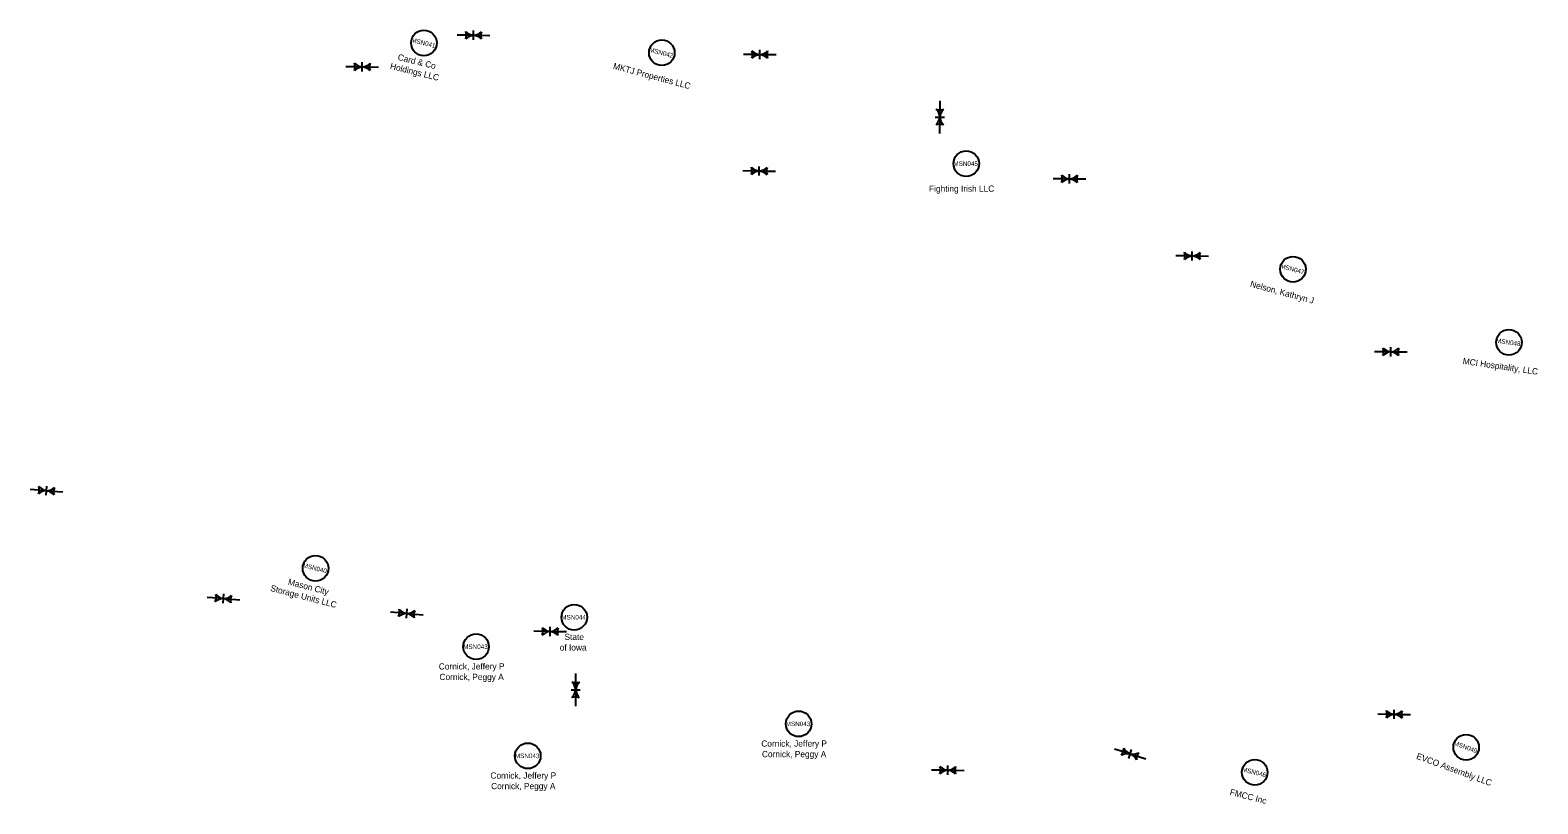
# Model space of a CAD drawing. Extents: x 4995262 to 4999253, y 3881150 to 3900196.
# Drawn here: x 4998411 to 4999235, y 3881150 to 3881573 of the extents above; entities that cross this region are included whole.
import ezdxf

# ---------------------------------------------------------------- set-up
doc = ezdxf.new("R2010")
doc.units = 0
doc.layers.add('NamedBoundary', color=7, linetype='Continuous')
doc.layers.add('SheetText', color=7, linetype='Continuous')

msp = doc.modelspace()

# ---------------------------------------------------------------- linework, layer by layer
at = {"layer": 'NamedBoundary'}
for centre in [(4998626.57, 3881565.83), (4998756.56, 3881560.46), (4998922.88, 3881499.86), (4999101.39, 3881442.16), (4999219.38, 3881402.24), (4998567.37, 3881278.73), (4998708.71, 3881251.99), (4998655.1, 3881235.88), (4998831.3, 3881193.71), (4998683.33, 3881176.23), (4999196.01, 3881180.91), (4999080.5, 3881167.23)]:
    msp.add_circle(centre, 7, dxfattribs=at)
at = {"layer": 'SheetText'}
for p, q in [((4998653.73, 3881570.02), (4998644.78, 3881570.06)), ((4998653.72, 3881567.48), (4998653.74, 3881572.55)), ((4998653.73, 3881570.02), (4998662.67, 3881569.97)), ((4998810.05, 3881556.94), (4998810.07, 3881562)), ((4998592.89, 3881552.71), (4998583.95, 3881552.75)), ((4998592.88, 3881550.18), (4998592.9, 3881555.24)), ((4998592.89, 3881552.71), (4998601.83, 3881552.67)), ((4998810.06, 3881559.47), (4998801.12, 3881559.51)), ((4998810.06, 3881559.47), (4998819, 3881559.43)), ((4998908.47, 3881525.32), (4998908.59, 3881534.26)), ((4998905.94, 3881525.35), (4998911, 3881525.29)), ((4998908.47, 3881525.32), (4998908.35, 3881516.38)), ((4998809.77, 3881495.83), (4998800.83, 3881495.88)), ((4998809.76, 3881493.3), (4998809.78, 3881498.37)), ((4998809.77, 3881495.83), (4998818.71, 3881495.79)), ((4998979.28, 3881488.99), (4998979.3, 3881494.05)), ((4998979.29, 3881491.52), (4998970.35, 3881491.56)), ((4998979.29, 3881491.52), (4998988.23, 3881491.48)), ((4999046.35, 3881449.41), (4999037.41, 3881449.45)), ((4999046.34, 3881446.88), (4999046.36, 3881451.94)), ((4999046.35, 3881449.41), (4999055.29, 3881449.37)), ((4999154.84, 3881397.02), (4999145.9, 3881397.04)), ((4999154.83, 3881394.48), (4999154.85, 3881399.55)), ((4999154.84, 3881397.02), (4999163.78, 3881396.99)), ((4998420.38, 3881321.14), (4998411.46, 3881321.8)), ((4998420.19, 3881318.62), (4998420.57, 3881323.66)), ((4998420.38, 3881321.14), (4998429.3, 3881320.48)), ((4998516.85, 3881259.63), (4998517.23, 3881264.68)), ((4998517.04, 3881262.16), (4998508.12, 3881262.83)), ((4998517.04, 3881262.16), (4998525.96, 3881261.48)), ((4998616.98, 3881251.46), (4998617.36, 3881256.5)), ((4998617.17, 3881253.98), (4998608.25, 3881254.66)), ((4998617.17, 3881253.98), (4998626.09, 3881253.3)), ((4998695.55, 3881244.19), (4998686.61, 3881244.28)), ((4998695.53, 3881241.66), (4998695.58, 3881246.72)), ((4998695.55, 3881244.19), (4998704.5, 3881244.11)), ((4998709.5, 3881212.33), (4998709.62, 3881221.27)), ((4998706.97, 3881212.36), (4998712.04, 3881212.29)), ((4998709.5, 3881212.33), (4998709.39, 3881203.38)), ((4999156.68, 3881198.91), (4999147.74, 3881198.98)), ((4999156.66, 3881196.38), (4999156.7, 3881201.44)), ((4999156.68, 3881198.91), (4999165.63, 3881198.84)), ((4999012.42, 3881177.27), (4999003.86, 3881179.86)), ((4999011.68, 3881174.85), (4999013.15, 3881179.69)), ((4999012.42, 3881177.27), (4999020.97, 3881174.67)), ((4998912.79, 3881168.37), (4998903.85, 3881168.45)), ((4998912.77, 3881165.84), (4998912.82, 3881170.9)), ((4998912.79, 3881168.37), (4998921.74, 3881168.29))]:
    msp.add_line(p, q, dxfattribs=at)
for centre, radius, start, end in [((4998644.13, 3881570.06), 5.68, 339.12989, 20.34353), ((4998654.47, 3881562.76), 7.29, 95.84257, 133.64981), ((4998654.54, 3881577.26), 7.29, 225.82361, 263.63086), ((4998652.99, 3881577.27), 7.29, 275.84257, 313.64981), ((4998652.92, 3881562.77), 7.29, 45.82361, 83.63086), ((4998663.32, 3881569.97), 5.68, 159.12989, 200.34353), ((4998800.46, 3881559.51), 5.68, 339.1317, 20.34534), ((4998810.87, 3881566.72), 7.29, 225.82542, 263.63267), ((4998809.32, 3881566.73), 7.29, 275.84437, 313.65162), ((4998819.66, 3881559.43), 5.68, 159.1317, 200.34534), ((4998583.29, 3881552.75), 5.68, 339.12989, 20.34353), ((4998593.63, 3881545.45), 7.29, 95.84257, 133.64981), ((4998593.7, 3881559.96), 7.29, 225.82361, 263.63086), ((4998592.15, 3881559.97), 7.29, 275.84257, 313.64981), ((4998592.08, 3881545.46), 7.29, 45.82361, 83.63086), ((4998602.49, 3881552.67), 5.68, 159.12989, 200.34353), ((4998810.8, 3881552.21), 7.29, 95.84437, 133.65162), ((4998809.25, 3881552.22), 7.29, 45.82542, 83.63267), ((4998901.21, 3881524.64), 7.29, 5.34157, 43.14881), ((4998908.6, 3881534.91), 5.68, 248.62889, 289.84253), ((4998915.71, 3881524.45), 7.29, 135.32261, 173.12986), ((4998901.23, 3881526.19), 7.29, 315.32261, 353.12986), ((4998908.34, 3881515.72), 5.68, 68.62889, 109.84253), ((4998915.73, 3881526), 7.29, 185.34157, 223.14881), ((4998800.17, 3881495.88), 5.68, 339.13243, 20.34607), ((4998810.51, 3881488.58), 7.29, 95.84511, 133.65235), ((4998810.58, 3881503.08), 7.29, 225.82615, 263.6334), ((4998809.03, 3881503.09), 7.29, 275.84511, 313.65235), ((4998808.96, 3881488.59), 7.29, 45.82615, 83.6334), ((4998819.37, 3881495.79), 5.68, 159.13243, 200.34607), ((4998969.69, 3881491.56), 5.68, 339.1317, 20.34534), ((4998980.03, 3881484.26), 7.29, 95.84437, 133.65162), ((4998980.1, 3881498.77), 7.29, 225.82542, 263.63267), ((4998978.55, 3881498.78), 7.29, 275.84437, 313.65162), ((4998978.48, 3881484.27), 7.29, 45.82542, 83.63267), ((4998988.89, 3881491.48), 5.68, 159.1317, 200.34534), ((4999036.75, 3881449.45), 5.68, 339.1317, 20.34534), ((4999047.09, 3881442.15), 7.29, 95.84437, 133.65162), ((4999047.16, 3881456.66), 7.29, 225.82542, 263.63267), ((4999045.61, 3881456.67), 7.29, 275.84437, 313.65162), ((4999045.54, 3881442.16), 7.29, 45.82542, 83.63267), ((4999055.95, 3881449.37), 5.68, 159.1317, 200.34534), ((4999145.24, 3881397.05), 5.68, 339.21749, 20.43113), ((4999155.59, 3881389.76), 7.29, 95.93016, 133.73741), ((4999155.64, 3881404.27), 7.29, 225.91121, 263.71846), ((4999154.09, 3881404.27), 7.29, 275.93016, 313.73741), ((4999154.04, 3881389.77), 7.29, 45.91121, 83.71846), ((4999164.44, 3881396.99), 5.68, 159.21749, 200.43113), ((4998410.81, 3881321.84), 5.68, 335.19079, 16.40442), ((4998420.62, 3881313.85), 7.29, 91.90346, 129.7107), ((4998421.69, 3881328.32), 7.29, 221.8845, 259.69175), ((4998420.14, 3881328.43), 7.29, 271.90346, 309.7107), ((4998419.07, 3881313.96), 7.29, 41.8845, 79.69175), ((4998429.95, 3881320.44), 5.68, 155.19079, 196.40442), ((4998507.47, 3881262.88), 5.68, 335.04604, 16.25967), ((4998518.36, 3881269.33), 7.29, 221.73975, 259.547), ((4998516.82, 3881269.45), 7.29, 271.75871, 309.56596), ((4998526.61, 3881261.43), 5.68, 155.04604, 196.25967), ((4998517.27, 3881254.87), 7.29, 91.75871, 129.56596), ((4998515.72, 3881254.98), 7.29, 41.73975, 79.547), ((4998607.6, 3881254.71), 5.68, 335.04604, 16.25967), ((4998618.49, 3881261.15), 7.29, 221.73975, 259.547), ((4998616.95, 3881261.27), 7.29, 271.75871, 309.56596), ((4998626.74, 3881253.25), 5.68, 155.04604, 196.25967), ((4998617.4, 3881246.69), 7.29, 91.75871, 129.56596), ((4998615.85, 3881246.81), 7.29, 41.73975, 79.547), ((4998685.96, 3881244.28), 5.68, 338.85358, 20.06722), ((4998696.26, 3881236.93), 7.29, 95.56625, 133.3735), ((4998696.4, 3881251.44), 7.29, 225.5473, 263.35454), ((4998694.85, 3881251.45), 7.29, 275.56625, 313.3735), ((4998694.71, 3881236.95), 7.29, 45.5473, 83.35454), ((4998705.15, 3881244.1), 5.68, 158.85358, 200.06722), ((4998702.24, 3881211.65), 7.29, 5.34157, 43.14881), ((4998709.63, 3881221.92), 5.68, 248.62889, 289.84253), ((4998716.75, 3881211.45), 7.29, 135.32261, 173.12986), ((4998702.26, 3881213.2), 7.29, 315.32261, 353.12986), ((4998709.38, 3881202.73), 5.68, 68.62889, 109.84253), ((4998716.77, 3881213), 7.29, 185.34157, 223.14881), ((4999147.09, 3881198.98), 5.68, 338.9544, 20.16804), ((4999157.4, 3881191.65), 7.29, 95.66707, 133.47432), ((4999157.51, 3881206.16), 7.29, 225.64812, 263.45537), ((4999155.96, 3881206.17), 7.29, 275.66707, 313.47432), ((4999155.85, 3881191.66), 7.29, 45.64812, 83.45537), ((4999166.28, 3881198.84), 5.68, 158.9544, 200.16804), ((4999003.23, 3881180.05), 5.68, 322.53174, 3.74537), ((4999011.05, 3881170.1), 7.29, 79.24441, 117.05166), ((4999015.26, 3881183.98), 7.29, 209.22545, 247.0327), ((4999013.78, 3881184.43), 7.29, 259.24441, 297.05166), ((4999009.57, 3881170.55), 7.29, 29.22545, 67.0327), ((4999021.6, 3881174.48), 5.68, 142.53174, 183.74537), ((4998903.2, 3881168.46), 5.68, 338.85358, 20.06722), ((4998913.5, 3881161.11), 7.29, 95.56625, 133.3735), ((4998913.64, 3881175.61), 7.29, 225.5473, 263.35454), ((4998912.09, 3881175.63), 7.29, 275.56625, 313.3735), ((4998911.95, 3881161.13), 7.29, 45.5473, 83.35454), ((4998922.39, 3881168.28), 5.68, 158.85358, 200.06722)]:
    msp.add_arc(centre, radius, start, end, dxfattribs=at)

# ---------------------------------------------------------------- texts
at = {"layer": 'NamedBoundary'}
for s, height, rotation, p in [('MSN041', 2.5, 346.06013, (4998619.49, 3881566.3)), ('MSN042', 2.5, 345.07021, (4998749.45, 3881561.06)), ('Holdings LLC', 3.4, 346.06013, (4998607.84, 3881551.7)), ('Card & Co', 3.4, 346.06013, (4998612.04, 3881556.6)), ('MKTJ Properties LLC', 3.4, 345.07021, (4998729.71, 3881551.74)), ('MSN047', 2.5, 344.77559, (4999094.25, 3881442.8)), ('Nelson, Kathryn J', 3.4, 344.77559, (4999077.74, 3881432.69)), ('MSN048', 2.5, 351.79996, (4999212.19, 3881402.01)), ('MCI Hospitality, LLC', 3.4, 351.79996, (4999193.97, 3881390.4)), ('MSN040', 2.5, 345.31281, (4998560.2, 3881279.32)), ('Mason City', 3.4, 345.31281, (4998552.08, 3881269.86)), ('Storage Units LLC', 3.4, 345.31281, (4998542.46, 3881266.42)), ('MSN049', 2.5, 339.78748, (4999188.93, 3881182.19)), ('EVCO Assembly LLC', 3.4, 339.78748, (4999168.46, 3881174.71)), ('MSN046', 2.5, 345.62332, (4999073.32, 3881167.78)), ('FMCC Inc', 3.4, 345.62332, (4999066.63, 3881154.95))]:
    msp.add_text(s, height=height, rotation=rotation, dxfattribs=at).set_placement(p)
for s, height, p in [('MSN045', 2.5, (4998915.83, 3881498.61)), ('Fighting Irish LLC', 3.4, (4998902.55, 3881484.52)), ('MSN044', 2.5, (4998701.61, 3881250.74)), ('State', 3.4, (4998703.41, 3881239.53)), ('MSN043', 2.5, (4998648.04, 3881234.63)), ('of Iowa', 3.4, (4998700.8, 3881233.77)), ('Cornick, Jeffery P', 3.4, (4998634.71, 3881223.42)), ('Cornick, Peggy A', 3.4, (4998635.09, 3881217.66)), ('MSN043', 2.5, (4998824.24, 3881192.46)), ('Cornick, Jeffery P', 3.4, (4998810.91, 3881181.24)), ('MSN043', 2.5, (4998676.27, 3881174.98)), ('Cornick, Peggy A', 3.4, (4998811.28, 3881175.48)), ('Cornick, Jeffery P', 3.4, (4998662.94, 3881163.77)), ('Cornick, Peggy A', 3.4, (4998663.31, 3881158.01))]:
    msp.add_text(s, height=height, dxfattribs=at).set_placement(p)

doc.saveas('drawing.dxf')
